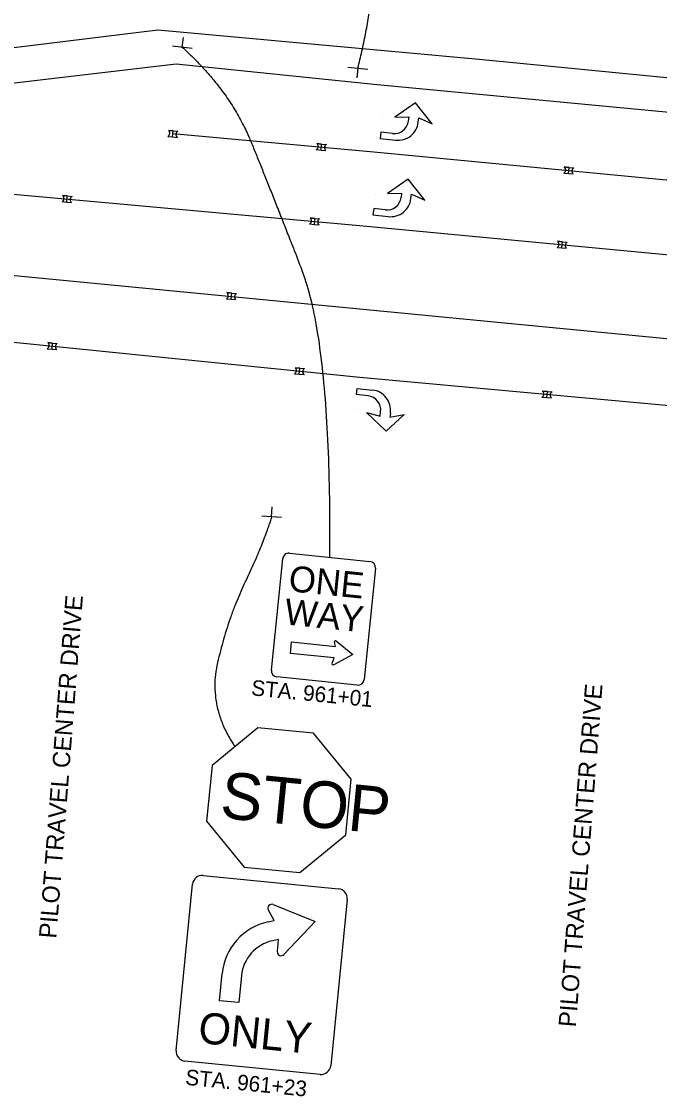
# Model space of a CAD drawing. Extents: x 1847379 to 1850904, y 217032 to 220169.
# Drawn here: x 1850210.2 to 1850312.9, y 218596.4 to 218769.3 of the extents above; entities that cross this region are included whole.
import ezdxf

# ---------------------------------------------------------------- set-up
doc = ezdxf.new("R2010")
doc.units = 0
for name, color, linetype in [('PM_P_Cells', 7, 'Continuous'), ('PM_P_Channelizing_Line', 7, 'Continuous'), ('PM_P_Edge_Line', 7, 'Continuous'), ('PM_P_Lane_Line', 7, 'Continuous'), ('SN_X_Public', 7, 'Continuous'), ('SN_X_Text', 7, 'Continuous')]:
    doc.layers.add(name, color=color, linetype=linetype)

msp = doc.modelspace()

# ---------------------------------------------------------------- linework, layer by layer
at = {"layer": 'PM_P_Cells'}
for p, q in [((1850273.64, 218756.22), (1850270.3, 218753.94)), ((1850276.3, 218752.88), (1850273.64, 218756.22)), ((1850268.36, 218753.83), (1850268.36, 218753.83)), ((1850270.3, 218753.94), (1850272.57, 218754)), ((1850272.57, 218754), (1850272.48, 218753.3)), ((1850274.08, 218753.15), (1850274.15, 218753.81)), ((1850274.15, 218753.81), (1850276.3, 218752.88)), ((1850276.3, 218752.88), (1850276.3, 218752.88)), ((1850234.64, 218751.73), (1850233.87, 218751.8)), ((1850233.87, 218751.8), (1850234.64, 218751.73)), ((1850234.55, 218750.76), (1850234.64, 218751.73)), ((1850234.64, 218751.73), (1850235.4, 218751.66)), ((1850268.08, 218751.52), (1850267.96, 218750.52)), ((1850269.93, 218751.3), (1850268.08, 218751.52)), ((1850233.78, 218750.83), (1850234.55, 218750.76)), ((1850233.78, 218750.83), (1850234.55, 218750.76)), ((1850234.55, 218750.76), (1850235.32, 218750.69)), ((1850258.52, 218749.61), (1850257.76, 218749.68)), ((1850257.76, 218749.68), (1850258.52, 218749.61)), ((1850258.44, 218748.64), (1850258.52, 218749.61)), ((1850258.52, 218749.61), (1850259.29, 218749.54)), ((1850267.96, 218750.52), (1850270.42, 218750.23)), ((1850257.67, 218748.71), (1850258.44, 218748.64)), ((1850257.67, 218748.71), (1850258.44, 218748.64)), ((1850258.44, 218748.64), (1850259.2, 218748.57)), ((1850297.49, 218744.95), (1850298.26, 218744.88)), ((1850297.49, 218744.95), (1850298.26, 218744.88)), ((1850298.35, 218745.85), (1850297.58, 218745.92)), ((1850297.58, 218745.92), (1850298.35, 218745.85)), ((1850298.26, 218744.88), (1850298.35, 218745.85)), ((1850298.26, 218744.88), (1850299.03, 218744.81)), ((1850298.35, 218745.85), (1850299.12, 218745.78)), ((1850272.46, 218743.95), (1850269.13, 218741.66)), ((1850275.13, 218740.61), (1850272.46, 218743.95)), ((1850217.6, 218741.26), (1850216.84, 218741.33)), ((1850216.84, 218741.33), (1850217.6, 218741.26)), ((1850217.52, 218740.29), (1850217.6, 218741.26)), ((1850217.6, 218741.26), (1850218.37, 218741.19)), ((1850267.18, 218741.56), (1850267.18, 218741.56)), ((1850269.13, 218741.66), (1850271.39, 218741.73)), ((1850271.39, 218741.73), (1850271.31, 218741.03)), ((1850272.9, 218740.87), (1850272.98, 218741.54)), ((1850272.98, 218741.54), (1850275.13, 218740.61)), ((1850216.75, 218740.36), (1850217.52, 218740.29)), ((1850216.75, 218740.36), (1850217.52, 218740.29)), ((1850217.52, 218740.29), (1850218.28, 218740.22)), ((1850266.91, 218739.24), (1850266.79, 218738.25)), ((1850268.76, 218739.02), (1850266.91, 218739.24)), ((1850275.13, 218740.61), (1850275.13, 218740.61)), ((1850257.44, 218737.66), (1850256.68, 218737.73)), ((1850256.68, 218737.73), (1850257.44, 218737.66)), ((1850257.36, 218736.69), (1850257.44, 218737.66)), ((1850257.44, 218737.66), (1850258.21, 218737.59)), ((1850266.79, 218738.25), (1850269.25, 218737.95)), ((1850256.59, 218736.76), (1850257.36, 218736.69)), ((1850256.59, 218736.76), (1850257.36, 218736.69)), ((1850257.36, 218736.69), (1850258.12, 218736.62)), ((1850297.27, 218733.9), (1850296.5, 218733.97)), ((1850296.5, 218733.97), (1850297.27, 218733.9)), ((1850297.18, 218732.92), (1850297.27, 218733.9)), ((1850297.27, 218733.9), (1850298.03, 218733.83)), ((1850296.41, 218732.99), (1850297.18, 218732.92)), ((1850296.41, 218732.99), (1850297.18, 218732.92)), ((1850297.18, 218732.92), (1850297.95, 218732.86)), ((1850244.06, 218725.64), (1850243.29, 218725.71)), ((1850243.29, 218725.71), (1850244.06, 218725.64)), ((1850243.97, 218724.67), (1850244.06, 218725.64)), ((1850244.06, 218725.64), (1850244.83, 218725.57)), ((1850243.2, 218724.74), (1850243.97, 218724.67)), ((1850243.2, 218724.74), (1850243.97, 218724.67)), ((1850243.97, 218724.67), (1850244.74, 218724.6)), ((1850214.37, 218716.69), (1850215.14, 218716.62)), ((1850214.37, 218716.69), (1850215.14, 218716.62)), ((1850215.22, 218717.6), (1850214.46, 218717.67)), ((1850214.46, 218717.67), (1850215.22, 218717.6)), ((1850215.14, 218716.62), (1850215.22, 218717.6)), ((1850215.14, 218716.62), (1850215.9, 218716.56)), ((1850215.22, 218717.6), (1850215.99, 218717.53)), ((1850255.02, 218713.57), (1850254.25, 218713.64)), ((1850254.25, 218713.64), (1850255.02, 218713.57)), ((1850254.93, 218712.59), (1850255.02, 218713.57)), ((1850255.02, 218713.57), (1850255.79, 218713.5)), ((1850254.16, 218712.66), (1850254.93, 218712.59)), ((1850254.16, 218712.66), (1850254.93, 218712.59)), ((1850254.93, 218712.59), (1850255.7, 218712.53)), ((1850264.15, 218709.33), (1850264.26, 218710.32)), ((1850264.26, 218710.32), (1850266.72, 218710.04)), ((1850294.85, 218709.82), (1850294.08, 218709.89)), ((1850294.08, 218709.89), (1850294.85, 218709.82)), ((1850294.76, 218708.85), (1850294.85, 218709.82)), ((1850294.85, 218709.82), (1850295.61, 218709.75)), ((1850266, 218709.12), (1850264.15, 218709.33)), ((1850293.99, 218708.92), (1850294.76, 218708.85)), ((1850293.99, 218708.92), (1850294.76, 218708.85)), ((1850294.76, 218708.85), (1850295.52, 218708.78)), ((1850263.88, 218707.01), (1850263.88, 218707.01)), ((1850268.94, 218703.41), (1850265.75, 218706.46)), ((1850265.75, 218706.46), (1850267.94, 218705.87)), ((1850267.94, 218705.87), (1850268.02, 218706.57)), ((1850269.6, 218706.35), (1850269.53, 218705.69)), ((1850271.83, 218706.1), (1850268.94, 218703.41)), ((1850269.53, 218705.69), (1850271.83, 218706.1)), ((1850271.83, 218706.1), (1850271.83, 218706.1))]:
    msp.add_line(p, q, dxfattribs=at)
for centre, radius, start, end in [((1850270.2, 218753.58), 2.3, 263.1824, 353.1824), ((1850270.81, 218753.49), 3.28, 263.1824, 354.0909), ((1850233.52, 218751.34), 0.576, 296.8063, 52.8586), ((1850233.52, 218751.34), 0.576, 296.8063, 52.8586), ((1850235.66, 218751.15), 0.576, 116.8063, 232.8586), ((1850257.41, 218749.22), 0.576, 296.8063, 52.8586), ((1850257.41, 218749.22), 0.576, 296.8063, 52.8586), ((1850259.55, 218749.03), 0.576, 116.8063, 232.8586), ((1850297.23, 218745.46), 0.576, 296.8063, 52.8586), ((1850297.23, 218745.46), 0.576, 296.8063, 52.8586), ((1850299.37, 218745.27), 0.576, 116.8063, 232.8586), ((1850216.49, 218740.87), 0.576, 296.8063, 52.8586), ((1850216.49, 218740.87), 0.576, 296.8063, 52.8586), ((1850218.63, 218740.68), 0.576, 116.8063, 232.8586), ((1850269.03, 218741.3), 2.3, 263.1824, 353.1824), ((1850269.64, 218741.21), 3.28, 263.1824, 354.0909), ((1850256.33, 218737.27), 0.576, 296.8063, 52.8586), ((1850256.33, 218737.27), 0.576, 296.8063, 52.8586), ((1850258.47, 218737.08), 0.576, 116.8063, 232.8586), ((1850296.15, 218733.51), 0.576, 296.8063, 52.8586), ((1850296.15, 218733.51), 0.576, 296.8063, 52.8586), ((1850298.29, 218733.31), 0.576, 116.8063, 232.8586), ((1850242.94, 218725.25), 0.576, 296.8063, 52.8586), ((1850242.94, 218725.25), 0.576, 296.8063, 52.8586), ((1850245.09, 218725.06), 0.576, 116.8063, 232.8586), ((1850214.11, 218717.21), 0.576, 296.8063, 52.8586), ((1850214.11, 218717.21), 0.576, 296.8063, 52.8586), ((1850216.25, 218717.01), 0.576, 116.8063, 232.8586), ((1850253.9, 218713.18), 0.576, 296.8063, 52.8586), ((1850253.9, 218713.18), 0.576, 296.8063, 52.8586), ((1850256.05, 218712.98), 0.576, 116.8063, 232.8586), ((1850266.35, 218706.78), 3.28, 352.5446, 83.453), ((1850293.73, 218709.43), 0.576, 296.8063, 52.8586), ((1850293.73, 218709.43), 0.576, 296.8063, 52.8586), ((1850295.87, 218709.24), 0.576, 116.8063, 232.8586), ((1850265.74, 218706.83), 2.3, 353.453, 83.453)]:
    msp.add_arc(centre, radius, start, end, dxfattribs=at)
at = {"layer": 'PM_P_Channelizing_Line'}
for points in [[(1850652.98, 218698.12), (1850615.27, 218701.75), (1850564.66, 218706.78), (1850513.12, 218712.05), (1850461.3, 218717.14), (1850408.88, 218722.34), (1850360.86, 218727.03), (1850313.39, 218731.82), (1850265.8, 218736.37), (1849979.48, 218762.27)], [(1850654.14, 218710.06), (1850616.44, 218713.69), (1850565.86, 218718.72), (1850514.32, 218723.99), (1850462.47, 218729.08), (1850410.06, 218734.29), (1850362.04, 218738.97), (1850314.56, 218743.77), (1850266.91, 218748.32), (1850234.59, 218751.24)], [(1850650.65, 218674.09), (1850566.02, 218682.53), (1850518.02, 218687.39), (1850471.03, 218692.07), (1850419.06, 218697.16), (1850371.65, 218702.19), (1850311.6, 218707.75), (1850264.65, 218712.06), (1850215.84, 218717), (1850171.13, 218721.51), (1850121.19, 218725.85), (1850066.37, 218730.8), (1850014.99, 218735.41), (1849965.69, 218739.72), (1849914.21, 218744.36), (1849896.49, 218746.14)]]:
    msp.add_lwpolyline(points, dxfattribs=at)
at = {"layer": 'PM_P_Edge_Line'}
for p, q in [((1850185.27, 218762.22), (1850232.15, 218767.99)), ((1850232.15, 218767.99), (1850283.89, 218763.25)), ((1850283.89, 218763.25), (1850334.84, 218758.27)), ((1850235.11, 218762.44), (1850183.58, 218756.39)), ((1850267.46, 218759.14), (1850235.11, 218762.44)), ((1850315.62, 218754.6), (1850267.46, 218759.14))]:
    msp.add_line(p, q, dxfattribs=at)
at = {"layer": 'PM_P_Lane_Line'}
msp.add_line((1849881.96, 218760.04), (1850650.78, 218685.87), dxfattribs=at)
at = {"layer": 'SN_X_Public'}
for p, q in [((1850236.11, 218765.17), (1850236.3, 218766.76)), ((1850237.7, 218764.99), (1850234.52, 218765.36)), ((1850262.76, 218761.98), (1850265.95, 218761.68)), ((1850264.35, 218761.83), (1850264.2, 218760.24)), ((1850250.47, 218689.65), (1850250.58, 218691.25)), ((1850252.07, 218689.54), (1850248.88, 218689.76)), ((1850253.36, 218683.8), (1850266.29, 218682.48)), ((1850250.44, 218664.99), (1850252.26, 218682.9)), ((1850267.18, 218681.39), (1850265.37, 218663.48)), ((1850253.51, 218667.67), (1850253.7, 218669.54)), ((1850253.7, 218669.54), (1850260.76, 218668.82)), ((1850260.76, 218668.8), (1850260.61, 218669.46)), ((1850260.94, 218669.67), (1850263.57, 218667.51)), ((1850260.56, 218666.95), (1850253.51, 218667.67)), ((1850260.2, 218666.14), (1850260.56, 218666.95)), ((1850263.57, 218667.51), (1850260.48, 218665.87)), ((1850264.27, 218662.58), (1850251.34, 218663.9)), ((1850248.27, 218655.72), (1850240.89, 218649.67)), ((1850257.23, 218654.84), (1850248.27, 218655.72)), ((1850263.28, 218647.46), (1850257.23, 218654.84)), ((1850240.89, 218649.67), (1850240.01, 218640.71)), ((1850262.4, 218638.51), (1850263.28, 218647.46)), ((1850240.01, 218640.71), (1850246.07, 218633.33)), ((1850255.02, 218632.45), (1850262.4, 218638.51)), ((1850246.07, 218633.33), (1850255.02, 218632.45)), ((1850250.73, 218627.29), (1850257.47, 218624.55)), ((1850250.91, 218624.72), (1850249.96, 218626.41)), ((1850249.94, 218624.51), (1850250.91, 218624.72)), ((1850257.47, 218624.55), (1850252.47, 218619.26)), ((1850251.57, 218621.67), (1850250.6, 218621.46)), ((1850251.4, 218619.75), (1850251.57, 218621.67)), ((1850242.09, 218611.83), (1850242.52, 218616.18)), ((1850245.63, 218615.87), (1850245.2, 218611.52)), ((1850245.2, 218611.52), (1850242.09, 218611.83))]:
    msp.add_line(p, q, dxfattribs=at)
for points in [[(1850239.46, 218631.97), (1850261.23, 218629.83)], [(1850235.12, 218603.82), (1850237.76, 218630.57)], [(1850262.64, 218628.12), (1850260, 218601.37)], [(1850258.3, 218599.97), (1850236.53, 218602.12)]]:
    msp.add_lwpolyline(points, dxfattribs=at)
for centre, radius, start, end in [((1850253.26, 218682.8), 1, 84.198, 174.198), ((1850266.19, 218681.49), 1, 354.198, 84.198), ((1850260.81, 218669.51), 0.208, 50.6221, 193.2614), ((1850251.44, 218664.89), 1, 174.198, 264.198), ((1850260.39, 218666.06), 0.208, 156.2746, 297.9235), ((1850264.37, 218663.58), 1, 264.198, 354.198), ((1850239.31, 218630.42), 1.56, 84.3781, 174.3781), ((1850261.08, 218628.27), 1.56, 354.3781, 84.3781), ((1850250.5, 218626.71), 0.625, 67.8128, 209.5846), ((1850251.95, 218615.25), 9.48, 102.2356, 174.3781), ((1850251.95, 218615.25), 6.35, 102.2394, 174.3781), ((1850252.02, 218619.69), 0.625, 174.8521, 316.6239), ((1850236.68, 218603.67), 1.56, 174.3781, 264.3781), ((1850258.45, 218601.53), 1.56, 264.3781, 354.3781)]:
    msp.add_arc(centre, radius, start, end, dxfattribs=at)
at = {"layer": 'SN_X_Text'}
for points in [[(1850264.35, 218761.83), (1850267.28, 218773.2), (1850267.55, 218798.02), (1850256.3, 218823.1), (1850257.64, 218833.35)], [(1850236.11, 218765.17), (1850243.8, 218758.19), (1850250.51, 218741.79), (1850260.04, 218717.25), (1850259.82, 218683.14)], [(1850250.47, 218689.65), (1850249.15, 218685.29), (1850243.44, 218673.37), (1850240.15, 218659.19), (1850244.58, 218652.69)]]:
    msp.add_open_spline(points, degree=2, dxfattribs=at)

# ---------------------------------------------------------------- texts
at = {"layer": 'SN_X_Public'}
for s, height, rotation, p in [('ONE', 4.172, 354.198, (1850253.09, 218677.71)), ('PILOT TRAVEL CENTER DRIVE', 2.8, 85.5355, (1850215.82, 218621.77)), ('WAY', 4.172, 354.198, (1850252.41, 218672.37)), ('PILOT TRAVEL CENTER DRIVE', 2.8, 85.5355, (1850299.43, 218607.51)), ('STOP', 7.5, 354.3781, (1850242.03, 218641.26)), ('ONLY', 5, 354.3781, (1850238.53, 218605.06))]:
    msp.add_text(s, height=height, rotation=rotation, dxfattribs=at).set_placement(p)
at = {"layer": 'SN_X_Text'}
for s, p in [('STA. 961+01', (1850247.12, 218660.96)), ('STA. 961+23', (1850236.51, 218598.32))]:
    msp.add_text(s, height=2.5, rotation=354.3781, dxfattribs=at).set_placement(p)

doc.saveas('drawing.dxf')
